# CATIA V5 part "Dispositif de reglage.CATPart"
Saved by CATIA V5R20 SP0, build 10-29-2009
Part number: Dispositif de reglage
Publications: "Face", "Arête", "Arête1", "Arête2", "Arête3"
Bounding box of the stored display mesh (mm): x -28.992 to 28.992, y 208.004 to 238.004, z 137.58 to 195.563
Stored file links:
  C:\Users\thinkmotion1\Desktop\Khaled_IAO_Pack2\IAO_2010_1412_jclement\Non_Optimise\Dispositif de reglage.CATPart
  F:\Colonel\Synthèse IAO\Synthese IAO.CATProduct
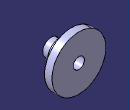
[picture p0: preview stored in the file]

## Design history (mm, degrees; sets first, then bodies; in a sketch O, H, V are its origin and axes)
Body1 (main body)
  Sketch1 on yz-plane, origin (0, 0, 0), H (0, 1, 0), V (0, 0, 1)
    axis line L1 (259.6921, 166.5716) -> (167.9415, 166.5716)
    line L2 (238.0039, 172.5716) -> (238.0039, 195.5716)
    line L3 (238.0039, 195.5716) -> (230.0039, 195.5716)
    line L4 (230.0039, 195.5716) -> (230.0039, 180.5716)
    line L5 (230.0039, 180.5716) -> (218.0039, 180.5716)
    line L6 (218.0039, 180.5716) -> (218.0039, 175.5716)
    line L7 (218.0039, 175.5716) -> (208.0039, 175.5716)
    line L8 (208.0039, 175.5716) -> (208.0039, 172.5716)
    line L9 (238.0039, 172.5716) -> (208.0039, 172.5716)
    distance L9 L1 = 6
    length L8 = 3
    length L7 = 10
    length L6 = 5
    length L5 = 12
    length L4 = 15
    length L3 = 8
    horizontal: L1 H, L3 H, L5 H, L7 H, L9 H
    vertical: L2 V, L4 V, L6 V, L8 V
  Shaft1: profile Sketch1, axis Sketch1.L1, angle 360
  Thread1: diameter 13.2, depth 30, pitch 1, on face of Shaft1 from Sketch1.L9, from face of Shaft1 from Sketch1.L8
